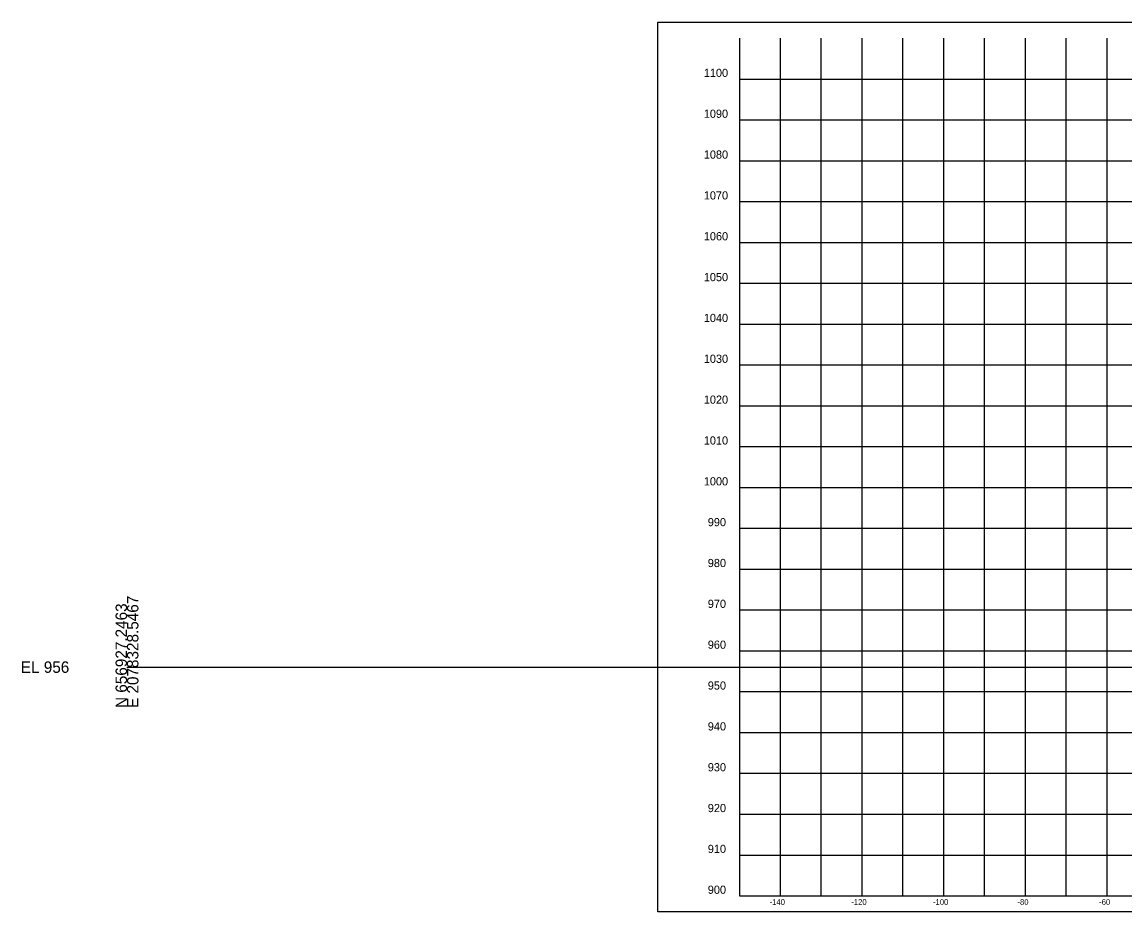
# Model space of a CAD drawing. Extents: x 80 to 2781, y 80 to 559.
# Drawn here: x 2152.5 to 2422.6, y 340.9 to 558.8 of the extents above; entities that cross this region are included whole.
import ezdxf

# ---------------------------------------------------------------- set-up
doc = ezdxf.new("R2010")
doc.units = 0
for name, color, linetype in [('DESIGN - SHEET - Corner Text', 7, 'Continuous'), ('DESIGN - SHEET - Light Grid', 7, 'Continuous'), ('DESIGN - SHEET - Linework', 7, 'Continuous'), ('DESIGN - SHEET - Plot Shape', 7, 'Continuous')]:
    doc.layers.add(name, color=color, linetype=linetype)

msp = doc.modelspace()

# ---------------------------------------------------------------- linework, layer by layer
at = {"layer": 'DESIGN - SHEET - Light Grid'}
msp.add_line((2178.23, 400.87), (2478.23, 400.87), dxfattribs=at)
at = {"layer": 'DESIGN - SHEET - Linework'}
for p, q in [((2338.23, 344.87), (2338.23, 554.87)), ((2348.23, 344.87), (2348.23, 554.87)), ((2358.23, 344.87), (2358.23, 554.87)), ((2368.23, 344.87), (2368.23, 554.87)), ((2378.23, 344.87), (2378.23, 554.87)), ((2388.23, 344.87), (2388.23, 554.87)), ((2398.23, 344.87), (2398.23, 554.87)), ((2408.23, 344.87), (2408.23, 554.87)), ((2418.23, 344.87), (2418.23, 554.87)), ((2328.23, 544.87), (2628.23, 544.87)), ((2328.23, 534.87), (2628.23, 534.87)), ((2328.23, 524.87), (2628.23, 524.87)), ((2328.23, 514.87), (2628.23, 514.87)), ((2328.23, 504.87), (2628.23, 504.87)), ((2328.23, 494.87), (2628.23, 494.87)), ((2328.23, 484.87), (2628.23, 484.87)), ((2328.23, 474.87), (2628.23, 474.87)), ((2328.23, 464.87), (2628.23, 464.87)), ((2328.23, 454.87), (2628.23, 454.87)), ((2328.23, 444.87), (2628.23, 444.87)), ((2328.23, 434.87), (2628.23, 434.87)), ((2328.23, 424.87), (2628.23, 424.87)), ((2328.23, 414.87), (2628.23, 414.87)), ((2328.23, 404.87), (2628.23, 404.87)), ((2328.23, 394.87), (2628.23, 394.87)), ((2328.23, 384.87), (2628.23, 384.87)), ((2328.23, 374.87), (2628.23, 374.87)), ((2328.23, 364.87), (2628.23, 364.87)), ((2328.23, 354.87), (2628.23, 354.87))]:
    msp.add_line(p, q, dxfattribs=at)
msp.add_lwpolyline([(2328.23, 554.87), (2328.23, 344.87), (2628.23, 344.87), (2628.23, 554.87)], dxfattribs=at)
at = {"layer": 'DESIGN - SHEET - Plot Shape'}
msp.add_lwpolyline([(2308.23, 558.81), (2648.23, 558.81), (2648.23, 340.93), (2308.23, 340.93)], close=True, dxfattribs=at)

# ---------------------------------------------------------------- texts
at = {"layer": 'DESIGN - SHEET - Corner Text'}
for s, height, p in [('1100', 2, (2319.47, 545.37)), ('1090', 2, (2319.47, 535.37)), ('1080', 2, (2319.47, 525.37)), ('1070', 2, (2319.47, 515.37)), ('1060', 2, (2319.47, 505.37)), ('1050', 2, (2319.47, 495.37)), ('1040', 2, (2319.47, 485.37)), ('1030', 2, (2319.47, 475.37)), ('1020', 2, (2319.47, 465.37)), ('1010', 2, (2319.47, 455.37)), ('1000', 2, (2319.47, 445.37)), ('990', 2, (2320.45, 435.37)), ('980', 2, (2320.45, 425.37)), ('970', 2, (2320.45, 415.37)), ('960', 2, (2320.45, 405.37)), ('950', 2, (2320.45, 395.37)), ('940', 2, (2320.45, 385.37)), ('930', 2, (2320.45, 375.37)), ('920', 2, (2320.45, 365.37)), ('910', 2, (2320.45, 355.37)), ('900', 2, (2320.45, 345.37)), ('-140', 1.4, (2335.6, 342.67)), ('-120', 1.4, (2355.6, 342.67)), ('-100', 1.4, (2375.6, 342.67)), ('-80', 1.4, (2396.28, 342.67)), ('-60', 1.4, (2416.28, 342.67))]:
    msp.add_text(s, height=height, dxfattribs=at).set_placement(p)
at = {"layer": 'DESIGN - SHEET - Light Grid'}
for s, p in [('N 656927.2463', (2178.23, 390.87)), ('E 2078328.5467', (2181.03, 390.87))]:
    msp.add_text(s, height=2.8, rotation=90, dxfattribs=at).set_placement(p)
msp.add_text('EL 956', height=2.8, dxfattribs=at).set_placement((2152.23, 399.47))

doc.saveas('drawing.dxf')
